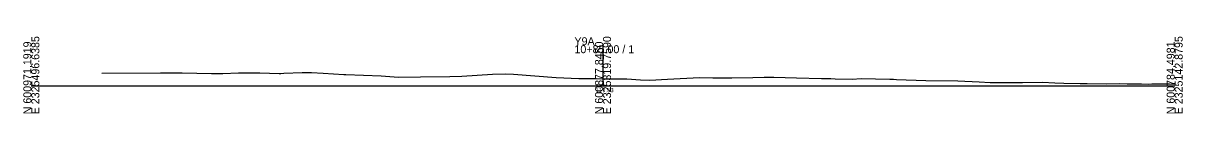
# Model space of a CAD drawing. Extents: x -26 to 2325310, y -10 to 600913.
# Drawn here: x 1397.2 to 1802.8, y -9.7 to 17.3 of the extents above; entities that cross this region are included whole.
import ezdxf

# ---------------------------------------------------------------- set-up
doc = ezdxf.new("R2010")
doc.units = 0
for name, color, linetype in [('Default', 7, 'Continuous'), ('Exist CMT Pavement', 7, 'Continuous'), ('Exist Cross Section Cell', 7, 'Continuous'), ('Exist XS Center Line Elevation Label', 7, 'Continuous'), ('Exist XS Ground Line', 7, 'Continuous'), ('Prop XS Earthwork Shape', 7, 'Continuous')]:
    doc.layers.add(name, color=color, linetype=linetype)

msp = doc.modelspace()

# ---------------------------------------------------------------- linework, layer by layer
at = {"layer": 'Exist CMT Pavement'}
msp.add_lwpolyline([(1600, 2.53), (1600, 2.63), (1600.1, 2.63), (1600.1, 2.53)], dxfattribs=at)
at = {"layer": 'Exist Cross Section Cell'}
for p, q in [((1600, 0), (1600, 14.29)), ((1400, 0), (1600, 0)), ((1600, 0), (1800, 0))]:
    msp.add_line(p, q, dxfattribs=at)
at = {"layer": 'Exist XS Ground Line'}
msp.add_lwpolyline([(1424.66, 4.51), (1445.22, 4.62), (1452.79, 4.55), (1463.07, 4.34), (1464.1, 4.35), (1465.09, 4.35), (1466.97, 4.38), (1472.49, 4.55), (1475.41, 4.59), (1479.89, 4.63), (1486.71, 4.39), (1487.3, 4.39), (1488.39, 4.44), (1494.7, 4.76), (1498.02, 4.69), (1502.1, 4.44), (1509.33, 3.98), (1510.06, 3.94), (1522.4, 3.48), (1528.46, 3.09), (1536.17, 3.17), (1546.47, 3.25), (1550.65, 3.44), (1556.02, 3.71), (1561.32, 4.12), (1565.88, 4.18), (1568.72, 4.09), (1583.65, 3), (1591.51, 2.63), (1597.57, 2.56), (1600, 2.53), (1601.23, 2.52), (1608.35, 2.42), (1613.11, 2.16), (1616.42, 2.02), (1622.55, 2.3), (1633.73, 2.9), (1638.39, 2.87), (1645.03, 2.79), (1652.46, 2.99), (1656.34, 3.06), (1659.82, 3.02), (1667.65, 2.86), (1676.4, 2.63), (1678.96, 2.56), (1679.75, 2.55), (1681.25, 2.53), (1687.15, 2.34), (1690.27, 2.58), (1700.35, 2.3), (1701.58, 2.31), (1702.68, 2.25), (1712.89, 1.84), (1724.19, 1.81), (1731.57, 1.41), (1735.5, 1.22), (1738.97, 1.23), (1745.53, 1.14), (1746.81, 1.14), (1753.77, 1.25), (1758.12, 1.08), (1761.17, 0.96), (1766.96, 0.86), (1768.58, 0.85), (1769.43, 0.82), (1775.98, 0.76), (1780.74, 0.78), (1783.38, 0.76), (1788.39, 0.69), (1790.78, 0.64), (1792.04, 0.69), (1798.18, 0.67), (1800, 0.65)], dxfattribs=at)
at = {"layer": 'Prop XS Earthwork Shape'}
msp.add_lwpolyline([(1600, 2.53), (1600, 2.63), (1600.1, 2.63), (1600.1, 2.53)], close=True, dxfattribs=at)

# ---------------------------------------------------------------- texts
at = {"layer": 'Default'}
msp.add_text('-', height=0.0001, dxfattribs=at).set_placement((1400, 0))
msp.add_text('-', height=0.0001, dxfattribs=at).set_placement((1400, 0))
at = {"layer": 'Exist Cross Section Cell'}
for s, p in [('E 2325496.6385', (1402.8, -10)), ('E 2325319.7590', (1602.8, -10)), ('E 2325142.8795', (1802.8, -10)), ('N 600971.1919', (1400, -10)), ('N 600877.8450', (1600, -10)), ('N 600784.4981', (1800, -10))]:
    msp.add_text(s, height=2.8, rotation=90, dxfattribs=at).set_placement(p)
for s, p in [('Y9A', (1590, 14.29)), ('10+85.00 / 1', (1590, 11.49))]:
    msp.add_text(s, height=2.8, dxfattribs=at).set_placement(p)
at = {"layer": 'Exist XS Center Line Elevation Label'}
msp.add_text('117.53', height=1.5, dxfattribs=at).set_placement((1597.37, -2.22))

doc.saveas('drawing.dxf')
